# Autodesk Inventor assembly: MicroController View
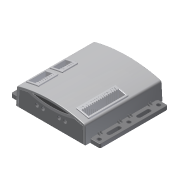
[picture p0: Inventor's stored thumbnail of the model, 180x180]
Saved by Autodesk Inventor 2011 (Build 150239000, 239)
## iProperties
Created: 2007-09
Part Number: MicroController View
Document SubType Name: Assembly
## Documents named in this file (9)
- C:\Data Folder\VEX 2011\Inventor Datasets\Unit 16\Components\MicroController View.iam
- C:\Data Folder\VEX 2011\Inventor Datasets\Unit 16\Components\MICROCONTROLLER-COVER-B.ipt
- C:\Data Folder\VEX 2011\Inventor Datasets\Unit 16\Components\MICROCONTROLLER-SWITCH.ipt
- C:\Data Folder\VEX 2011\Inventor Datasets\Unit 16\Components\MICROCONTROLLER-TOP.ipt
- C:\Data Folder\VEX 2011\Inventor Datasets\Unit 16\Components\MICROCONTROLLER-COVER-C.ipt
- C:\Data Folder\VEX 2011\Inventor Datasets\Unit 16\Components\MICROCONTROLLER-COVER-A.ipt
- C:\Data Folder\VEX 2011\Inventor Datasets\Unit 16\Components\MICROCONTROLLER-FRONT.ipt
- C:\Data Folder\VEX 2011\Inventor Datasets\Unit 16\Components\MICROCONTROLLER-PCB.iam
- C:\Data Folder\VEX 2011\Inventor Datasets\Unit 16\Components\MICROCONTROLLER-BOT.ipt
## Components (8 placed, 8 different names)
1. MICROCONTROLLER-COVER-B
2. MICROCONTROLLER-SWITCH
3. MICROCONTROLLER-TOP — Flush:1, Mate:1, Mate:2, Mate:3, Mate:4
4. MICROCONTROLLER-COVER-C
5. MICROCONTROLLER-COVER-A — Mate:3, Mate:4, Mate:5
6. MICROCONTROLLER-FRONT
7. MICROCONTROLLER-PCB [sub-assembly]
8. MICROCONTROLLER-BOT — Flush:1, Mate:1, Mate:2, Mate:5
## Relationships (6: Mate 5, Flush 1)
- Flush:1: MICROCONTROLLER-TOP ↔ MICROCONTROLLER-BOT
- Mate:1: MICROCONTROLLER-TOP ↔ MICROCONTROLLER-BOT
- Mate:2: MICROCONTROLLER-TOP ↔ MICROCONTROLLER-BOT
- Mate:3: MICROCONTROLLER-TOP ↔ MICROCONTROLLER-COVER-A
- Mate:4: MICROCONTROLLER-TOP ↔ MICROCONTROLLER-COVER-A
- Mate:5: MICROCONTROLLER-COVER-A ↔ MICROCONTROLLER-BOT
